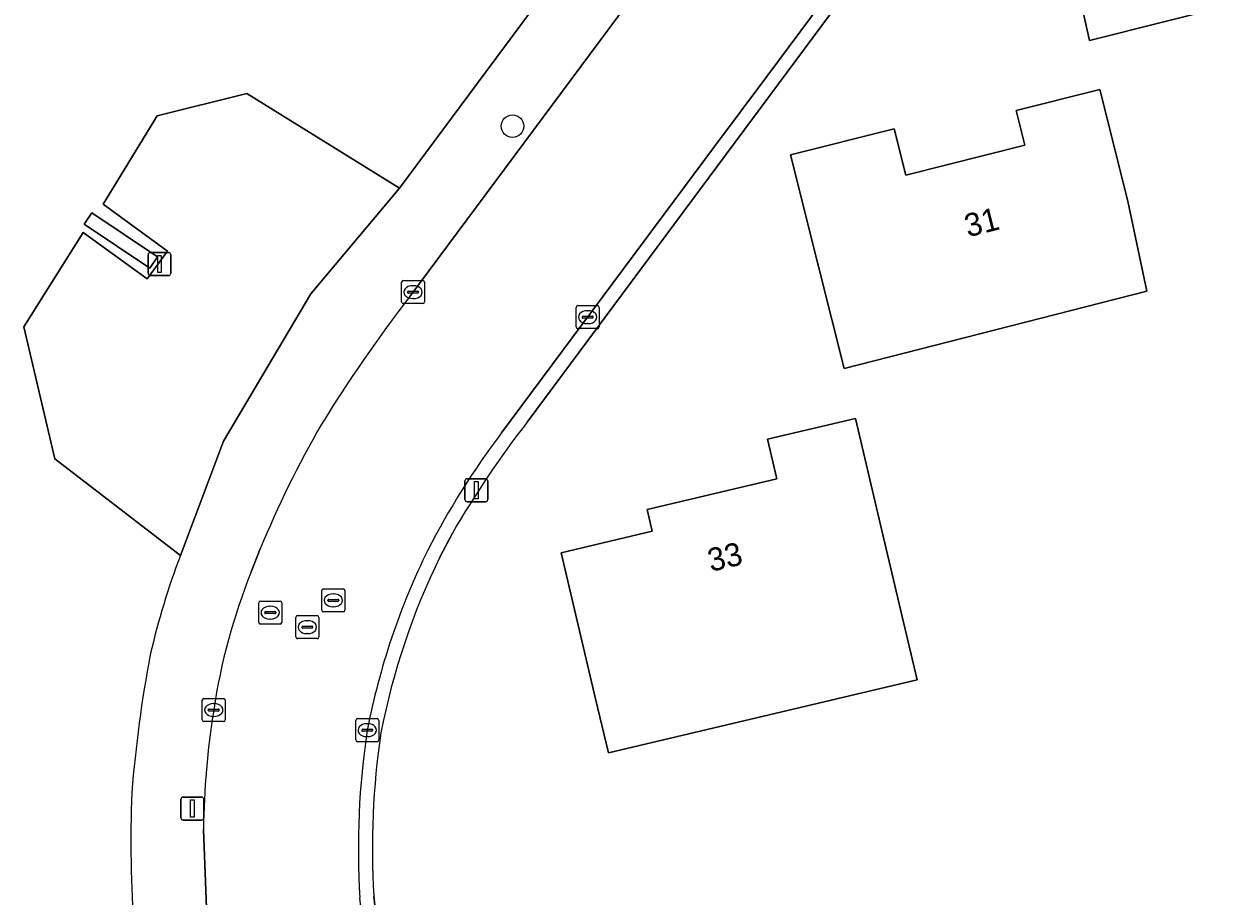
# Model space of a CAD drawing. Extents: x 157648 to 158502, y 379212 to 380938.
# Drawn here: x 158068.3 to 158120, y 380530.4 to 380568.3 of the extents above; entities that cross this region are included whole.
import ezdxf

# ---------------------------------------------------------------- set-up
doc = ezdxf.new("R2010")
doc.units = 0
for name, color, linetype in [('IMGEO_Boom', 7, 'Continuous'), ('IMGEO_Erf', 7, 'Continuous'), ('IMGEO_Groenvoorziening', 7, 'Continuous'), ('IMGEO_Haag', 7, 'Continuous'), ('IMGEO_Hek', 7, 'Continuous'), ('IMGEO_Kolk', 7, 'Continuous'), ('IMGEO_Lichtmast', 7, 'Continuous'), ('IMGEO_Pand', 7, 'Continuous'), ('IMGEO_Pand_nummerreeks', 7, 'Continuous'), ('IMGEO_Rijbaan_lokaal_open', 7, 'Continuous'), ('IMGEO_Rioolput', 7, 'Continuous'), ('IMGEO_Voetpad_open', 7, 'Continuous')]:
    doc.layers.add(name, color=color, linetype=linetype)

msp = doc.modelspace()

# ---------------------------------------------------------------- linework, layer by layer
at = {"layer": 'IMGEO_Boom'}
msp.add_circle((158089.492, 380563.814), 0.489, dxfattribs=at)
at = {"layer": 'IMGEO_Erf'}
for points in [[(158069.616, 380549.366), (158068.269, 380555.098), (158070.851, 380559.203), (158073.631, 380557.179), (158074.514, 380558.387), (158071.722, 380560.424), (158074.062, 380564.268), (158077.955, 380565.234), (158084.588, 380561.116), (158131.522, 380624.317)], [(158140.58, 380618.873), (158090.13, 380550.967)], [(158075.069, 380545.171), (158069.616, 380549.366)], [(158086.883, 380546.14), (158086.354, 380545.122)], [(158083.47, 380530.375), (158084.108, 380524.698), (158091.931, 380459.649)]]:
    msp.add_lwpolyline(points, dxfattribs=at)
for points in [[(158127.767, 380570.872), (158114.566, 380567.532), (158113.55, 380572.072), (158112.458, 380576.951), (158116.821, 380578.047), (158117.314, 380576.087), (158122.433, 380577.374), (158122.041, 380578.932), (158125.752, 380579.865), (158126.845, 380574.986)], [(158116.221, 380560.553), (158117.043, 380556.643), (158103.898, 380553.295), (158102.787, 380557.716), (158101.568, 380562.565), (158106.074, 380563.697), (158106.579, 380561.687), (158111.755, 380562.988), (158111.377, 380564.491), (158115.002, 380565.402)], [(158070.889, 380559.559), (158071.223, 380560.057), (158074.073, 380558.143), (158073.739, 380557.645)], [(158105.541, 380546.256), (158106.483, 380542.274), (158107.075, 380539.774), (158093.659, 380536.6), (158093.105, 380538.943), (158091.604, 380545.287), (158095.565, 380546.224), (158095.342, 380547.17), (158100.978, 380548.503), (158100.573, 380550.218), (158104.39, 380551.121)]]:
    msp.add_lwpolyline(points, close=True, dxfattribs=at)
for centre, radius, start, end in [((158125.636, 380523.577), 44.843, 142.3532, 149.7914), ((158106.611, 380533.243), 33.722, 159.2856, 166.9199), ((158113.922, 380531.589), 30.711, 153.8533, 168.9764), ((158128.409, 380530.501), 55.621, 169.251, 175.4807), ((158118.209, 380532.415), 34.799, 171.6619, 183.3603), ((158125.506, 380532.746), 52.588, 177.6699, 184.2628)]:
    msp.add_arc(centre, radius, start, end, dxfattribs=at)
at = {"layer": 'IMGEO_Groenvoorziening'}
msp.add_lwpolyline([(158070.889, 380559.559), (158073.739, 380557.645), (158074.073, 380558.143), (158071.223, 380560.057)], close=True, dxfattribs=at)
at = {"layer": 'IMGEO_Haag'}
msp.add_lwpolyline([(158070.889, 380559.559), (158073.739, 380557.645), (158074.073, 380558.143), (158071.223, 380560.057)], close=True, dxfattribs=at)
at = {"layer": 'IMGEO_Hek'}
for points in [[(158086.354, 380545.122), (158086.883, 380546.14)], [(158084.108, 380524.698), (158083.47, 380530.375)]]:
    msp.add_lwpolyline(points, dxfattribs=at)
for centre, radius, start, end in [((158113.922, 380531.589), 30.711, 153.8533, 168.9764), ((158118.209, 380532.415), 34.799, 171.6619, 183.3603)]:
    msp.add_arc(centre, radius, start, end, dxfattribs=at)
at = {"layer": 'IMGEO_Kolk'}
for p, q in [((158084.675, 380556.182), (158084.675, 380557.034)), ((158084.75, 380557.108), (158085.602, 380557.108)), ((158085.676, 380557.034), (158085.676, 380556.182)), ((158084.934, 380556.602), (158084.934, 380556.614)), ((158085.372, 380556.565), (158084.974, 380556.565)), ((158084.977, 380556.651), (158085.375, 380556.651)), ((158085.163, 380556.888), (158085.188, 380556.888)), ((158085.418, 380556.614), (158085.418, 380556.602)), ((158085.602, 380556.108), (158084.75, 380556.108)), ((158085.186, 380556.328), (158085.161, 380556.328)), ((158092.333, 380556.021), (158093.185, 380556.021)), ((158092.258, 380555.095), (158092.258, 380555.947)), ((158092.517, 380555.515), (158092.517, 380555.527)), ((158092.56, 380555.564), (158092.958, 380555.564)), ((158092.746, 380555.801), (158092.771, 380555.801)), ((158093.001, 380555.527), (158093.001, 380555.515)), ((158093.259, 380555.947), (158093.259, 380555.095)), ((158093.185, 380555.021), (158092.333, 380555.021)), ((158092.955, 380555.478), (158092.557, 380555.478)), ((158092.769, 380555.241), (158092.744, 380555.241)), ((158076.093, 380538.959), (158076.945, 380538.959)), ((158076.018, 380538.033), (158076.018, 380538.885)), ((158076.277, 380538.453), (158076.277, 380538.465)), ((158076.715, 380538.416), (158076.317, 380538.416)), ((158076.32, 380538.502), (158076.718, 380538.502)), ((158076.506, 380538.739), (158076.531, 380538.739)), ((158076.761, 380538.465), (158076.761, 380538.453)), ((158077.019, 380538.885), (158077.019, 380538.033)), ((158076.945, 380537.959), (158076.093, 380537.959)), ((158076.529, 380538.179), (158076.504, 380538.179)), ((158082.686, 380537.158), (158082.686, 380538.01)), ((158082.761, 380538.084), (158083.613, 380538.084)), ((158083.687, 380538.01), (158083.687, 380537.158)), ((158082.945, 380537.578), (158082.945, 380537.59)), ((158083.383, 380537.541), (158082.985, 380537.541)), ((158082.988, 380537.627), (158083.386, 380537.627)), ((158083.174, 380537.864), (158083.199, 380537.864)), ((158083.429, 380537.59), (158083.429, 380537.578)), ((158083.613, 380537.084), (158082.761, 380537.084)), ((158083.197, 380537.304), (158083.172, 380537.304))]:
    msp.add_line(p, q, dxfattribs=at)
for points in [[(158084.675, 380556.182), (158084.675, 380557.034)], [(158084.75, 380557.108), (158085.602, 380557.108)], [(158085.676, 380557.034), (158085.676, 380556.182)], [(158085.602, 380556.108), (158084.75, 380556.108)], [(158092.333, 380556.021), (158093.185, 380556.021)], [(158092.258, 380555.095), (158092.258, 380555.947)], [(158093.259, 380555.947), (158093.259, 380555.095)], [(158093.185, 380555.021), (158092.333, 380555.021)], [(158076.093, 380538.959), (158076.945, 380538.959)], [(158076.018, 380538.033), (158076.018, 380538.885)], [(158077.019, 380538.885), (158077.019, 380538.033)], [(158076.945, 380537.959), (158076.093, 380537.959)], [(158082.686, 380537.158), (158082.686, 380538.01)], [(158082.761, 380538.084), (158083.613, 380538.084)], [(158083.687, 380538.01), (158083.687, 380537.158)], [(158083.613, 380537.084), (158082.761, 380537.084)]]:
    msp.add_lwpolyline(points, dxfattribs=at)
for centre, radius, start, end in [((158084.752, 380557.032), 0.0765, 91.552, 178.448), ((158084.752, 380557.032), 0.0765, 91.552, 178.448), ((158085.6, 380557.032), 0.0765, 1.552, 88.448), ((158085.6, 380557.032), 0.0765, 1.552, 88.448), ((158084.974, 380556.611), 0.0403, 85.8775, 175.7526), ((158084.971, 380556.601), 0.0366, 178.938, 274.7102), ((158085.375, 380556.608), 0.043, 264.8664, 352.4533), ((158085.379, 380556.613), 0.0386, 1.7309, 96.639), ((158084.752, 380556.184), 0.0765, 181.552, 268.448), ((158084.752, 380556.184), 0.0765, 181.552, 268.448), ((158085.6, 380556.184), 0.0765, 271.552, 358.448), ((158085.6, 380556.184), 0.0765, 271.552, 358.448), ((158092.335, 380555.945), 0.0765, 91.552, 178.448), ((158092.335, 380555.945), 0.0765, 91.552, 178.448), ((158093.183, 380555.945), 0.0765, 1.552, 88.448), ((158093.183, 380555.945), 0.0765, 1.552, 88.448), ((158092.557, 380555.524), 0.0403, 85.8775, 175.7526), ((158092.554, 380555.514), 0.0366, 178.938, 274.7102), ((158092.958, 380555.521), 0.043, 264.8664, 352.4533), ((158092.962, 380555.526), 0.0386, 1.7309, 96.639), ((158092.335, 380555.097), 0.0765, 181.552, 268.448), ((158092.335, 380555.097), 0.0765, 181.552, 268.448), ((158093.183, 380555.097), 0.0765, 271.552, 358.448), ((158093.183, 380555.097), 0.0765, 271.552, 358.448), ((158076.095, 380538.883), 0.0765, 91.552, 178.448), ((158076.095, 380538.883), 0.0765, 91.552, 178.448), ((158076.943, 380538.883), 0.0765, 1.552, 88.448), ((158076.943, 380538.883), 0.0765, 1.552, 88.448), ((158076.317, 380538.462), 0.0403, 85.8775, 175.7526), ((158076.314, 380538.452), 0.0366, 178.938, 274.7102), ((158076.718, 380538.459), 0.043, 264.8664, 352.4533), ((158076.722, 380538.464), 0.0386, 1.7309, 96.639), ((158076.095, 380538.035), 0.0765, 181.552, 268.448), ((158076.095, 380538.035), 0.0765, 181.552, 268.448), ((158076.943, 380538.035), 0.0765, 271.552, 358.448), ((158076.943, 380538.035), 0.0765, 271.552, 358.448), ((158082.763, 380538.008), 0.0765, 91.552, 178.448), ((158082.763, 380538.008), 0.0765, 91.552, 178.448), ((158083.611, 380538.008), 0.0765, 1.552, 88.448), ((158083.611, 380538.008), 0.0765, 1.552, 88.448), ((158082.985, 380537.587), 0.0403, 85.8775, 175.7526), ((158082.982, 380537.577), 0.0366, 178.938, 274.7102), ((158083.386, 380537.584), 0.043, 264.8664, 352.4533), ((158083.39, 380537.589), 0.0386, 1.7309, 96.639), ((158082.763, 380537.16), 0.0765, 181.552, 268.448), ((158082.763, 380537.16), 0.0765, 181.552, 268.448), ((158083.611, 380537.16), 0.0765, 271.552, 358.448), ((158083.611, 380537.16), 0.0765, 271.552, 358.448)]:
    msp.add_arc(centre, radius, start, end, dxfattribs=at)
for centre, major_axis, ratio, start_param, end_param in [((158085.162, 380556.608), (-0.387, 0.002), 0.722429, 4.712389, 7.853982), ((158085.187, 380556.608), (-0.39, 0.002), 0.717154, 1.570796, 4.712389), ((158092.745, 380555.521), (-0.387, 0.002), 0.722429, 4.712389, 7.853982), ((158092.77, 380555.521), (-0.39, 0.002), 0.717154, 1.570796, 4.712389), ((158076.505, 380538.459), (-0.387, 0.002), 0.722429, 4.712389, 7.853982), ((158076.53, 380538.459), (-0.39, 0.002), 0.717154, 1.570796, 4.712389), ((158083.173, 380537.584), (-0.387, 0.002), 0.722429, 4.712389, 7.853982), ((158083.198, 380537.584), (-0.39, 0.002), 0.717154, 1.570796, 4.712389)]:
    msp.add_ellipse(centre, major_axis=major_axis, ratio=ratio, start_param=start_param, end_param=end_param, dxfattribs=at)
at = {"layer": 'IMGEO_Lichtmast'}
for p, q in [((158073.664, 380557.429), (158073.664, 380558.229)), ((158073.664, 380558.229), (158073.664, 380557.429)), ((158073.764, 380558.329), (158074.554, 380558.329)), ((158074.554, 380558.329), (158073.764, 380558.329)), ((158074.654, 380558.229), (158074.654, 380557.429)), ((158074.654, 380557.429), (158074.654, 380558.229)), ((158074.554, 380557.329), (158073.764, 380557.329)), ((158073.764, 380557.329), (158074.554, 380557.329)), ((158087.432, 380547.606), (158087.432, 380548.406)), ((158087.432, 380548.406), (158087.432, 380547.606)), ((158087.532, 380548.506), (158088.322, 380548.506)), ((158088.322, 380548.506), (158087.532, 380548.506)), ((158088.422, 380548.406), (158088.422, 380547.606)), ((158088.422, 380547.606), (158088.422, 380548.406)), ((158088.322, 380547.506), (158087.532, 380547.506)), ((158087.532, 380547.506), (158088.322, 380547.506)), ((158075.094, 380533.781), (158075.094, 380534.581)), ((158075.094, 380534.581), (158075.094, 380533.781)), ((158075.194, 380534.681), (158075.984, 380534.681)), ((158075.984, 380534.681), (158075.194, 380534.681)), ((158076.084, 380534.581), (158076.084, 380533.781)), ((158076.084, 380533.781), (158076.084, 380534.581)), ((158075.984, 380533.681), (158075.194, 380533.681)), ((158075.194, 380533.681), (158075.984, 380533.681))]:
    msp.add_line(p, q, dxfattribs=at)
for points in [[(158074.084, 380558.204), (158074.234, 380558.204), (158074.234, 380557.454), (158074.084, 380557.454), (158074.084, 380558.204)], [(158087.852, 380548.381), (158088.002, 380548.381), (158088.002, 380547.631), (158087.852, 380547.631), (158087.852, 380548.381)], [(158075.514, 380534.556), (158075.664, 380534.556), (158075.664, 380533.806), (158075.514, 380533.806), (158075.514, 380534.556)]]:
    msp.add_lwpolyline(points, dxfattribs=at)
for centre, start, end in [((158073.764, 380558.229), 90, 180), ((158073.764, 380558.229), 90, 180), ((158074.554, 380558.229), 0, 90), ((158074.554, 380558.229), 360, 90), ((158073.764, 380557.429), 180, 270), ((158073.764, 380557.429), 180, 270), ((158074.554, 380557.429), 270, 0), ((158074.554, 380557.429), 270, 0), ((158087.532, 380548.406), 90, 180), ((158087.532, 380548.406), 90, 180), ((158088.322, 380548.406), 0, 90), ((158088.322, 380548.406), 360, 90), ((158087.532, 380547.606), 180, 270), ((158087.532, 380547.606), 180, 270), ((158088.322, 380547.606), 270, 0), ((158088.322, 380547.606), 270, 0), ((158075.194, 380534.581), 90, 180), ((158075.194, 380534.581), 90, 180), ((158075.984, 380534.581), 0, 90), ((158075.984, 380534.581), 360, 90), ((158075.194, 380533.781), 180, 270), ((158075.194, 380533.781), 180, 270), ((158075.984, 380533.781), 270, 0), ((158075.984, 380533.781), 270, 0)]:
    msp.add_arc(centre, 0.1, start, end, dxfattribs=at)
at = {"layer": 'IMGEO_Pand'}
for points in [[(158113.55, 380572.072), (158114.566, 380567.532), (158127.767, 380570.872), (158126.845, 380574.986), (158125.752, 380579.865), (158122.041, 380578.932), (158122.433, 380577.374), (158117.314, 380576.087), (158116.821, 380578.047), (158112.458, 380576.951)], [(158116.221, 380560.553), (158115.002, 380565.402), (158111.377, 380564.491), (158111.755, 380562.988), (158106.579, 380561.687), (158106.074, 380563.697), (158101.568, 380562.565), (158102.787, 380557.716), (158103.898, 380553.295), (158117.043, 380556.643)], [(158105.541, 380546.256), (158104.39, 380551.121), (158100.573, 380550.218), (158100.978, 380548.503), (158095.342, 380547.17), (158095.565, 380546.224), (158091.604, 380545.287), (158093.105, 380538.943), (158093.659, 380536.6), (158107.075, 380539.774), (158106.483, 380542.274)]]:
    msp.add_lwpolyline(points, close=True, dxfattribs=at)
at = {"layer": 'IMGEO_Rijbaan_lokaal_open'}
for points in [[(158135.53, 380624.378), (158123.165, 380607.755), (158119.072, 380602.259), (158111.202, 380591.638), (158107.086, 380586.099), (158098.128, 380574.013), (158094.943, 380569.745), (158085.035, 380556.423)], [(158089.025, 380550.498), (158098.266, 380562.93), (158100.542, 380565.978), (158107.373, 380575.162), (158110.981, 380580.03), (158119.02, 380590.852), (158121.722, 380594.507), (158129.96, 380605.535), (158132.676, 380609.174), (158140.435, 380619.693)], [(158078.538, 380545.453), (158078.149, 380544.46)], [(158076.07, 380533.27), (158076.245, 380528.73), (158082.958, 380529.523), (158082.866, 380530.302)]]:
    msp.add_lwpolyline(points, dxfattribs=at)
for centre, radius, start, end in [((158137.517, 380516.087), 66.191, 142.45526, 148.32029), ((158118.898, 380528.981), 43.591, 149.8902, 157.798), ((158116.288, 380529.781), 34.241, 142.769, 152.8633), ((158113.682, 380531.675), 31.062, 153.7799, 169.0338), ((158102.397, 380534.652), 26.156, 157.977, 171.6308), ((158111.482, 380532.82), 35.415, 170.8376, 179.2715), ((158117.182, 380532.437), 34.382, 171.3911, 183.5608)]:
    msp.add_arc(centre, radius, start, end, dxfattribs=at)
at = {"layer": 'IMGEO_Rioolput'}
for p, q in [((158081.212, 380542.796), (158081.212, 380543.648)), ((158081.287, 380543.722), (158082.139, 380543.722)), ((158082.213, 380543.648), (158082.213, 380542.796)), ((158078.472, 380542.264), (158078.472, 380543.116)), ((158078.547, 380543.19), (158079.399, 380543.19)), ((158079.473, 380543.116), (158079.473, 380542.264)), ((158081.471, 380543.216), (158081.471, 380543.228)), ((158081.909, 380543.179), (158081.511, 380543.179)), ((158081.514, 380543.265), (158081.912, 380543.265)), ((158081.7, 380543.502), (158081.725, 380543.502)), ((158081.955, 380543.228), (158081.955, 380543.216)), ((158078.731, 380542.684), (158078.731, 380542.696)), ((158079.169, 380542.647), (158078.771, 380542.647)), ((158078.774, 380542.733), (158079.172, 380542.733)), ((158078.96, 380542.97), (158078.985, 380542.97)), ((158079.215, 380542.696), (158079.215, 380542.684)), ((158080.158, 380542.558), (158081.01, 380542.558)), ((158082.139, 380542.722), (158081.287, 380542.722)), ((158081.723, 380542.942), (158081.698, 380542.942)), ((158079.399, 380542.19), (158078.547, 380542.19)), ((158078.983, 380542.41), (158078.958, 380542.41)), ((158080.083, 380541.632), (158080.083, 380542.484)), ((158080.342, 380542.052), (158080.342, 380542.064)), ((158080.385, 380542.101), (158080.783, 380542.101)), ((158080.571, 380542.338), (158080.596, 380542.338)), ((158080.826, 380542.064), (158080.826, 380542.052)), ((158081.084, 380542.484), (158081.084, 380541.632)), ((158081.01, 380541.558), (158080.158, 380541.558)), ((158080.78, 380542.015), (158080.382, 380542.015)), ((158080.594, 380541.778), (158080.569, 380541.778))]:
    msp.add_line(p, q, dxfattribs=at)
for points in [[(158081.212, 380542.796), (158081.212, 380543.648)], [(158081.287, 380543.722), (158082.139, 380543.722)], [(158082.213, 380543.648), (158082.213, 380542.796)], [(158078.472, 380542.264), (158078.472, 380543.116)], [(158078.547, 380543.19), (158079.399, 380543.19)], [(158079.473, 380543.116), (158079.473, 380542.264)], [(158080.158, 380542.558), (158081.01, 380542.558)], [(158082.139, 380542.722), (158081.287, 380542.722)], [(158079.399, 380542.19), (158078.547, 380542.19)], [(158080.083, 380541.632), (158080.083, 380542.484)], [(158081.084, 380542.484), (158081.084, 380541.632)], [(158081.01, 380541.558), (158080.158, 380541.558)]]:
    msp.add_lwpolyline(points, dxfattribs=at)
for centre, radius, start, end in [((158081.289, 380543.646), 0.0765, 91.552, 178.448), ((158081.289, 380543.646), 0.0765, 91.552, 178.448), ((158082.137, 380543.646), 0.0765, 1.552, 88.448), ((158082.137, 380543.646), 0.0765, 1.552, 88.448), ((158078.549, 380543.114), 0.0765, 91.552, 178.448), ((158078.549, 380543.114), 0.0765, 91.552, 178.448), ((158079.397, 380543.114), 0.0765, 1.552, 88.448), ((158079.397, 380543.114), 0.0765, 1.552, 88.448), ((158081.511, 380543.225), 0.0403, 85.8775, 175.7526), ((158081.508, 380543.215), 0.0366, 178.938, 274.7102), ((158081.912, 380543.222), 0.043, 264.8664, 352.4533), ((158081.916, 380543.227), 0.0386, 1.7309, 96.639), ((158078.771, 380542.693), 0.0403, 85.8775, 175.7526), ((158078.768, 380542.683), 0.0366, 178.938, 274.7102), ((158079.172, 380542.69), 0.043, 264.8664, 352.4533), ((158079.176, 380542.695), 0.0386, 1.7309, 96.639), ((158080.16, 380542.482), 0.0765, 91.552, 178.448), ((158080.16, 380542.482), 0.0765, 91.552, 178.448), ((158081.008, 380542.482), 0.0765, 1.552, 88.448), ((158081.008, 380542.482), 0.0765, 1.552, 88.448), ((158081.289, 380542.798), 0.0765, 181.552, 268.448), ((158081.289, 380542.798), 0.0765, 181.552, 268.448), ((158082.137, 380542.798), 0.0765, 271.552, 358.448), ((158082.137, 380542.798), 0.0765, 271.552, 358.448), ((158078.549, 380542.266), 0.0765, 181.552, 268.448), ((158078.549, 380542.266), 0.0765, 181.552, 268.448), ((158079.397, 380542.266), 0.0765, 271.552, 358.448), ((158079.397, 380542.266), 0.0765, 271.552, 358.448), ((158080.382, 380542.061), 0.0403, 85.8775, 175.7526), ((158080.379, 380542.051), 0.0366, 178.938, 274.7102), ((158080.783, 380542.058), 0.043, 264.8664, 352.4533), ((158080.787, 380542.063), 0.0386, 1.7309, 96.639), ((158080.16, 380541.634), 0.0765, 181.552, 268.448), ((158080.16, 380541.634), 0.0765, 181.552, 268.448), ((158081.008, 380541.634), 0.0765, 271.552, 358.448), ((158081.008, 380541.634), 0.0765, 271.552, 358.448)]:
    msp.add_arc(centre, radius, start, end, dxfattribs=at)
for centre, major_axis, ratio, start_param, end_param in [((158081.699, 380543.222), (-0.387, 0.002), 0.722429, 4.712389, 7.853982), ((158081.724, 380543.222), (-0.39, 0.002), 0.717154, 1.570796, 4.712389), ((158078.959, 380542.69), (-0.387, 0.002), 0.722429, 4.712389, 7.853982), ((158078.984, 380542.69), (-0.39, 0.002), 0.717154, 1.570796, 4.712389), ((158080.57, 380542.058), (-0.387, 0.002), 0.722429, 4.712389, 7.853982), ((158080.595, 380542.058), (-0.39, 0.002), 0.717154, 1.570796, 4.712389)]:
    msp.add_ellipse(centre, major_axis=major_axis, ratio=ratio, start_param=start_param, end_param=end_param, dxfattribs=at)
at = {"layer": 'IMGEO_Voetpad_open'}
for points in [[(158131.522, 380624.317), (158084.588, 380561.116), (158080.733, 380556.539), (158076.937, 380550.138), (158075.069, 380545.171)], [(158140.435, 380619.693), (158132.676, 380609.174), (158129.96, 380605.535), (158121.722, 380594.507), (158119.02, 380590.852), (158110.981, 380580.03), (158107.373, 380575.162), (158100.542, 380565.978), (158098.266, 380562.93), (158089.025, 380550.498)], [(158090.13, 380550.967), (158140.58, 380618.873)], [(158085.035, 380556.423), (158094.943, 380569.745), (158098.128, 380574.013), (158107.086, 380586.099), (158111.202, 380591.638), (158119.072, 380602.259)], [(158086.354, 380545.122), (158086.883, 380546.14)], [(158078.149, 380544.46), (158078.538, 380545.453)], [(158091.201, 380403.997), (158086.642, 380441.77), (158086.089, 380446.282), (158084.501, 380459.454), (158084.064, 380463.2), (158083.878, 380464.74), (158083.435, 380468.487), (158082.23, 380478.604), (158081.782, 380482.399), (158080.477, 380493.331), (158079.926, 380497.842), (158078.254, 380511.803), (158077.715, 380516.353), (158076.245, 380528.73), (158076.07, 380533.27)], [(158084.108, 380524.698), (158083.47, 380530.375)]]:
    msp.add_lwpolyline(points, dxfattribs=at)
msp.add_lwpolyline([(158084.588, 380561.116), (158077.955, 380565.234), (158074.062, 380564.268), (158071.722, 380560.424), (158074.514, 380558.387), (158073.631, 380557.179), (158070.851, 380559.203), (158068.269, 380555.098), (158069.616, 380549.366), (158075.069, 380545.171), (158076.937, 380550.138), (158080.733, 380556.539)], close=True, dxfattribs=at)
for centre, radius, start, end in [((158137.517, 380516.087), 66.191, 142.45526, 148.32029), ((158118.898, 380528.981), 43.591, 149.8902, 157.798), ((158125.636, 380523.577), 44.843, 142.3532, 149.7914), ((158116.288, 380529.781), 34.241, 142.769, 152.8633), ((158106.611, 380533.243), 33.722, 159.2856, 166.9199), ((158113.682, 380531.675), 31.062, 153.7799, 169.0338), ((158113.922, 380531.589), 30.711, 153.8533, 168.9764), ((158102.397, 380534.652), 26.156, 157.977, 171.6308), ((158128.409, 380530.501), 55.621, 169.251, 175.4807), ((158111.482, 380532.82), 35.415, 170.8376, 179.2715), ((158117.182, 380532.437), 34.382, 171.3911, 183.5608), ((158118.209, 380532.415), 34.799, 171.6619, 183.3603), ((158125.506, 380532.746), 52.588, 177.6699, 184.2628)]:
    msp.add_arc(centre, radius, start, end, dxfattribs=at)

# ---------------------------------------------------------------- texts
at = {"layer": 'IMGEO_Pand_nummerreeks'}
for s, rotation, p in [('31', 14.1092, (158109.275, 380558.983)), ('33', 13.3041, (158098.11, 380544.455))]:
    msp.add_text(s, height=1, rotation=rotation, dxfattribs=at).set_placement(p)

doc.saveas('drawing.dxf')
